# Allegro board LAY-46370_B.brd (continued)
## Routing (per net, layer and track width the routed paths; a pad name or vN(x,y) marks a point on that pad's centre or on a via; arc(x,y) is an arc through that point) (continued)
DSI_DP3: length 80.5
  TOP w0.091: J1.97 90.29,106.96 90.23,106.9 90.23,106.54 90.54,106.22 v1(90.71,106.22) ; v1(31.53,124.47) 31.69,124.63 31.69,124.99 31.61,125.07 U39.6 U39.5 31.61,127.68 31.89,127.96 31.89,128.8 31.66,129.03 J14.B17
  L3_IN1 w0.084: v1(90.71,106.22) 90.9,106.03 91.22,106.03 91.46,105.79 91.46,104.41 88.76,101.71 65.05,101.71 47.69,119.08 36.19,119.08 31.69,123.59 31.69,124.31 v1(31.53,124.47)
DSI_EN: length 58.2
  TOP w0.102: v1(76.4,113.07) 76.82,112.65 76.82,111.21 76.69,111.08 J1.30
  TOP w0.109: J14.A11 36.06,134.06 37.18,135.17 45.34,135.17 49.73,130.79 v1(49.73,124.44)
  BOTTOM w0.109: v1(76.4,113.07) 76.32,112.98 74.17,112.98 71.31,115.84 58.33,115.84 v1(49.73,124.44)
DSI_NINT: length 3.4
  TOP w0.102: J14.B9 38.06,126.72 R304.1
DSI_PWM: length 3.3
  TOP w0.102: R305.1 38.86,126.5 J14.B8
DSI_TS_NINT: length 48.6
  TOP w0.102: v1(38.06,124.96) 37.81,125.2 R304.2 ; v1(76.39,111.49) 76.29,111.39 J1.28
  BOTTOM w0.109: v1(38.06,124.96) 38.06,124.13 47.58,114.61 57.64,114.61 63.7,108.55 73.45,108.55 v1(76.39,111.49)
DSI_TS_SCL: length 3.6
  TOP w0.102: J14.B11 36.46,127.27 R167.1
DSI_TS_SDA: length 3.5
  TOP w0.102: J14.B10 37.26,127.01 R166.1
EARC_N_HPD: length 83.4
  TOP w0.091: TP88.1 160.81,132.73 160.81,132.42 159.72,131.33 159.72,125.54 126.52,92.33 126.52,78.56 120.63,72.67 116.59,72.67 116.53,72.6 J4.53
  TOP w0.102: C162.1 160.8,133.85 160.8,133.53 TP88.1
EARC_P_UTIL: length 83.4
  TOP w0.091: J4.55 116.53,73 116.59,72.94 120.52,72.94 126.25,78.67 126.25,92.44 159.45,125.65 159.45,131.44 160.54,132.53 160.54,132.88 160.33,133.1 TP87.1
  TOP w0.102: TP87.1 160.42,133.66 160.42,134.01 C161.1
ECSPI2_MISO: length 73
  TOP w0.109: J4.37 116.47,69.4 116.5,69.37 146.8,69.37 158.22,80.79 161.18,80.79 165.26,76.71 179.11,76.71 180.45,75.37 U55.4
ECSPI2_MISO_3V3: length 8.3
  TOP w0.109: J21.21 187.14,77.56 184.95,75.37 U55.8
ECSPI2_MOSI: length 72.7
  TOP w0.102: U55.3 181.46,75.77 181.4,75.71 180.81,75.71 v1(180.36,76.16)
  TOP w0.109: J4.35 146.88,69 158.27,80.4 160.91,80.4 165.18,76.14 v1(178.95,76.14)
  BOTTOM w0.102: v1(178.95,76.14) 178.97,76.16 v1(180.36,76.16)
ECSPI2_MOSI_3V3: length 9.9
  TOP w0.109: J21.19 188.05,80.1 185.83,77.87 185.83,76.74 184.87,75.77 U55.9
ECSPI2_SCLK: length 72.7
  TOP w0.109: J4.31 147.34,68.2 158.83,79.69 160.58,79.69 165.3,74.97 U55.5
ECSPI2_SCLK_3V3: length 7.4
  TOP w0.109: U55.7 186.57,74.97 186.61,75.02 J21.23
ECSPI2_SS0: length 72.8
  TOP w0.102: U55.2 v1(181.13,76.17)
  TOP w0.109: v1(178.94,75.5) 165.27,75.5 160.77,80 158.42,80 147.03,68.6 J4.33
  BOTTOM w0.102: v1(181.13,76.17) 180.45,75.5 v1(178.94,75.5)
ECSPI2_SS0_3V3: length 27
  TOP w0.109: U55.10 184.54,76.17 185.25,76.88 185.25,78.14 188.51,81.39 198.27,81.39 198.78,80.89 198.78,76.14 197.66,75.02 J21.24
EN_SNK1: length 20.9
  TOP w0.102: R64.2 49.91,24.63 Q2.3
  TOP w0.109: v1(50.94,28.33) 50.94,28.26 51.71,27.49 51.71,25.94 51.49,25.72 R65.1 49.93,25.72 R64.2
  TOP w0.203: U14.F1 60.51,34.75 v1(60.69,34.93)
  BOTTOM w0.109: v1(60.69,34.93) 61.52,34.09 61.52,33.5 60.83,32.81 58.41,32.81 53.94,28.33 v1(50.94,28.33)
EN_SRC1: length 2.2
  TOP w0.203: U14.G1 60.48,35.49 R55.2
ENET1_EVENT_IN: length 3
  TOP w0.109: v1(105.05,67.08) 104.65,67.08 R317.2
  BOTTOM w0.102: TP42.1 105.62,67.08 v1(105.05,67.08)
ENET1_EVENT_OUT: length 1.8
  TOP w0.109: v1(105.05,66.5) 105.02,66.5 R318.2
  BOTTOM w0.102: v1(105.05,66.5) 104.33,66.5 TP56.1
ENET1_MDC: length 55.1
  TOP w0.102: J3.86 105.82,65.28 106.59,66.04 v1(106.64,66.04)
  TOP w0.109: R110.2 v1(89.34,25.64)
  L6_IN2 w0.114: v1(89.34,25.64) 89.97,25.64 93.07,28.74 93.07,40.26 109.52,56.71 109.52,64.32 107.56,66.28 106.87,66.28 v1(106.64,66.04)
ENET1_MDIO: length 52.6
  TOP w0.102: v1(106.61,65.46) 106.54,65.46 106.11,65.02 106.11,64.03 106.22,63.92 J3.88
  TOP w0.109: R111.2 v1(89.24,27.62) 89.25,27.63 R100.1
  L6_IN2 w0.114: v1(106.61,65.46) 106.77,65.3 108.15,65.3 109.14,64.31 109.14,57.04 92.69,40.59 92.69,29.77 90.54,27.62 v1(89.24,27.62)
ENET1_NINT: length 48.5
  TOP w0.102: U26.31 79.37,30.49 v1(77.39,32.47)
  TOP w0.109: U4.12 117.33,33.8 v1(116.72,34.4) ; R114.1 76.72,34.67 76.72,33.13 v1(77.39,32.47)
  BOTTOM w0.109: v1(116.72,34.4) 116.44,34.12 79.03,34.12 v1(77.39,32.47)
ENET1_NRST: length 41.4
  TOP w0.109: U26.12 85.75,27.29 86.56,26.48 86.56,24.18 v1(86.9,23.83) R113.1 ; v1(110,24.9) 113.57,28.46 113.57,32.23 113.92,32.58 U4.14
  BOTTOM w0.109: v1(86.9,23.83) 87.3,23.44 90.44,23.44 90.6,23.6 108.7,23.6 v1(110,24.9)
ENET1_RD0: length 39.5
  TOP w0.102: v1(106.61,64.88) 106.65,64.88 107.06,64.47 107.06,63.84 107.02,63.81 J3.92
  TOP w0.109: R105.2 v1(82.83,37.57)
  L6_IN2 w0.114: v1(82.83,37.57) 82.83,37.95 103.87,58.99 103.87,62.17 106.58,64.88 v1(106.61,64.88)
ENET1_RD1: length 38.9
  TOP w0.109: R103.2 83.92,37.65 v1(83.95,37.67) ; J3.94 107.42,63.81 107.33,63.91 107.33,64.57 v1(107.44,64.68)
  L6_IN2 w0.114: v1(83.95,37.67) 83.95,38.44 104.18,58.67 104.18,61.14 107.28,64.24 107.28,64.52 v1(107.44,64.68)
ENET1_RD2: length 38.5
  TOP w0.109: J3.96 107.82,64.05 v1(107.78,64.1) ; R102.2 87.76,35.34 v1(87.71,35.39)
  L6_IN2 w0.114: v1(107.78,64.1) 105.57,61.89 105.57,59.39 87.71,41.52 v1(87.71,35.39)
ENET1_RD3: length 42.5
  TOP w0.109: v1(108.02,64.69) 108.22,64.49 J3.98 ; v1(88.64,35.41) 88.99,35.05 R106.2
  L6_IN2 w0.114: v1(108.02,64.69) 108.23,64.48 108.23,63.88 106,61.65 106,59.22 88.21,41.43 88.21,38.8 88.34,38.68 88.84,38.68 88.97,38.55 88.97,38.29 88.84,38.17 88.34,38.17 88.21,38.04 88.21,37.79 88.34,37.66 88.84,37.66 88.97,37.53 88.97,37.28 88.84,37.15 88.34,37.15 88.21,37.02 88.21,35.84 v1(88.64,35.41)
ENET1_RX_CTL: length 41
  TOP w0.109: v1(107.79,59.52) 107.79,59.69 107.82,59.72 J3.95 ; v1(88.91,39.37) 82.86,39.37 80.39,36.9 R107.2
  L6_IN2 w0.114: v1(107.79,59.52) 107.33,59.06 106.37,59.06 88.91,41.61 v1(88.91,39.37)
ENET1_RXC: length 40
  TOP w0.102: v1(79.86,36.2) C99.1 R108.2
  TOP w0.109: J3.73 v1(103.42,59.54)
  L6_IN2 w0.114: v1(79.86,36.2) 79.86,36.33 83.01,39.49 83.8,39.49 85.12,40.81 85.12,40.99 84.97,41.14 84.97,41.32 85.15,41.5 85.33,41.5 85.48,41.35 85.66,41.35 85.84,41.53 85.84,41.71 85.66,41.89 85.66,42.07 85.84,42.25 86.02,42.25 86.2,42.07 86.38,42.07 86.56,42.25 86.56,42.43 86.38,42.6 86.38,42.78 86.56,42.96 86.74,42.96 86.92,42.79 87.1,42.79 87.28,42.97 87.28,43.15 87.1,43.32 87.1,43.5 87.28,43.68 87.46,43.68 87.64,43.51 87.82,43.51 88,43.69 88,43.87 87.82,44.04 87.82,44.22 88,44.4 88.18,44.4 88.36,44.23 88.54,44.23 103.42,59.11 v1(103.42,59.54)
ENET1_RXC/PHYAD1: length 8.8
  TOP w0.109: U26.27 81.96,31.54 82.07,31.65 82.07,32.25 80.89,33.43 79.69,33.43 R108.1 78.09,33.96 R119.1 77.73,33.96 77.51,34.19 77.51,35.63 R439.2
ENET1_RXCTL/PHYAD2: length 4.3
  TOP w0.102: R126.1 R107.1
  TOP w0.109: R126.1 81.62,33.17 82.36,32.44 U26.26
ENET1_RXD0/RXDLY: length 6.9
  TOP w0.102: U26.25 82.76,33.9 R125.1 ; R118.2 R105.1
  TOP w0.109: R125.1 83.24,33.98 83.34,34.08 83.34,35.7 R105.1
ENET1_RXD1/TXDLY: length 7.2
  TOP w0.102: R103.1 R117.2 85.01,35.64 84.59,35.23 84.59,34.11 84.45,33.97 R124.1
  TOP w0.109: R124.1 83.16,33.17 U26.24
ENET1_RXD2/PLLOFF: length 6
  TOP w0.102: R120.2 83.56,32.21 U26.23
  TOP w0.109: R120.2 R128.1 R102.1
ENET1_RXD3/PHYAD0: length 8.9
  TOP w0.102: R127.2 90.09,33.96 R106.1
  TOP w0.109: U26.22 83.96,32.01 85.08,33.13 88.16,33.13 R106.1 ; R438.1 91.15,33.96 R127.2
ENET1_TD0: length 44.4
  TOP w0.102: v1(105.07,55.94) 103.92,57.09 103.92,59.69 103.82,59.78 J3.75
  TOP w0.109: v1(91.52,30.05) 91.29,30.29 90.29,30.29 89.15,29.15 86.22,29.15 85.68,29.69 U26.18
  L6_IN2 w0.114: v1(105.07,55.94) 105.07,55.81 90.64,41.39 90.64,30.92 91.51,30.05 v1(91.52,30.05)
ENET1_TD1: length 43
  TOP w0.102: J3.77 104.22,59.8 104.15,59.72 104.15,57.47 v1(105.08,56.54)
  TOP w0.109: U26.17 85.57,29.29 85.98,28.88 89.52,28.88 v1(90.39,29.76)
  L6_IN2 w0.114: v1(105.08,56.54) 105.04,56.54 90.3,41.81 90.3,29.85 v1(90.39,29.76)
ENET1_TD2: length 43.4
  TOP w0.102: J3.81 105.02,59.7 105.11,59.61 v1(105.11,57.18)
  TOP w0.109: U26.16 85.55,28.89 85.83,28.61 89.93,28.61 v1(90.39,29.08)
  L6_IN2 w0.114: v1(105.11,57.18) 105.09,57.18 89.95,42.04 89.95,29.57 90.39,29.13 v1(90.39,29.08)
ENET1_TD3: length 44.9
  TOP w0.102: v1(106.69,57.41) 106.63,57.41 105.52,58.52 105.52,59.83 105.42,59.93 J3.83
  TOP w0.109: U26.15 85.48,28.49 85.62,28.34 90.38,28.34 90.98,28.94 v1(90.98,29.05)
  L6_IN2 w0.114: v1(90.98,29.05) 91.44,29.05 92.29,29.91 92.29,41.03 106.69,55.43 v1(106.69,57.41)
ENET1_TX_CTL: length 43.6
  TOP w0.102: v1(106.66,57.99) 106.65,57.99 105.82,58.82 J3.85
  TOP w0.109: U26.19 85.65,30.09 86.33,29.41 88.92,29.41 90.2,30.69 v1(91.51,30.69)
  L6_IN2 w0.114: v1(91.51,30.69) 91.54,30.69 91.94,31.09 91.94,41.37 106.25,55.67 106.25,57.6 106.65,57.99 v1(106.66,57.99)
ENET1_TXC: length 43.4
  TOP w0.102: J3.87 106.22,60 106.13,59.91 106.13,59.13 v1(106.67,58.59)
  TOP w0.109: v1(91.49,31.28) 90.32,31.28 88.68,29.65 86.49,29.65 85.65,30.49 U26.20
  L6_IN2 w0.114: v1(91.49,31.28) 91.04,31.74 91.04,41.19 105.82,55.97 105.82,57.78 106.63,58.59 v1(106.67,58.59)
ENET_MDC: length 73.4
  TOP w0.102: v1(110.94,71.73) 110.94,71.86 111.29,72.2 J4.52
  TOP w0.109: v1(107.78,26.45) 107.69,26.35 R79.2 ; v1(89.28,24.51) 89.22,24.57 R424.2
  L6_IN2 w0.114: v1(110.94,71.73) 110.94,71.77 111.42,72.25 112.35,72.25 113.06,71.54 113.06,41.47 109.6,38.01 109.6,34.81 109.04,34.25 109.04,27.69 107.8,26.45 v1(107.78,26.45)
  BOTTOM w0.109: v1(89.28,24.51) 89.69,24.1 105.44,24.1 v1(107.78,26.45)
ENET_MDIO: length 74.5
  TOP w0.102: J4.54 111,72.6 110.36,71.96 v1(110.36,71.61) ; R85.1 v1(107.89,27.23)
  TOP w0.109: R80.2 107.12,27.64 107.53,27.23 v1(107.89,27.23) ; R425.2 v1(89.33,26.67)
  L6_IN2 w0.114: v1(107.89,27.23) 108.45,27.8 108.45,34.36 109.02,34.93 109.02,38.12 112.64,41.74 112.64,70.69 112.12,71.22 110.68,71.22 110.36,71.54 v1(110.36,71.61)
  BOTTOM w0.109: v1(107.89,27.23) 105.04,24.39 91.61,24.39 v1(89.33,26.67)
ENET_NINT: length 29
  TOP w0.109: U4.13 116.72,33.59 v1(116.68,33.62) ; R84.1 96.77,35.61 v1(96.77,33.58) 97.76,32.59 97.76,31.37 98.67,30.46 U23.31
  BOTTOM w0.109: v1(116.68,33.62) 116.51,33.8 96.99,33.8 v1(96.77,33.58)
ENET_NRST: length 20.1
  TOP w0.109: U4.15 114.29,32.18 113.89,31.78 113.89,28.1 110.13,24.35 106.59,24.35 106.33,24.6 R83.1 105.64,25.16 105.18,25.63 105.18,26.52 104.44,27.26 U23.12
ENET_RD0: length 55.4
  TOP w0.102: v1(111.55,77.75) 111.55,77.81 111.95,78.2 J4.82
  TOP w0.109: R73.2 102.78,34.7 v1(102.77,34.71)
  L6_IN2 w0.114: v1(111.55,77.75) 111.55,78.01 110.97,78.6 109.94,78.6 108.15,76.81 108.15,66.92 110.29,64.78 110.29,46.13 109.61,45.46 109.61,45.28 109.96,44.94 109.96,44.76 109.78,44.58 109.6,44.58 109.25,44.92 109.07,44.92 108.9,44.74 108.9,44.56 109.24,44.22 109.24,44.04 109.06,43.86 108.88,43.86 108.54,44.2 108.36,44.2 104.96,40.81 104.96,37.89 102.77,35.7 v1(102.77,34.71)
ENET_RD1: length 55
  TOP w0.102: J4.84 111.75,78.6 110.97,77.82 v1(110.97,77.76)
  TOP w0.109: R72.2 v1(103.84,34.72)
  L6_IN2 w0.114: v1(110.97,77.76) 110.97,77.9 110.67,78.2 110.16,78.2 108.54,76.59 108.54,66.97 110.66,64.85 110.66,44.77 108.83,42.94 108.65,42.94 108.36,43.23 108.18,43.23 108,43.05 108,42.87 108.29,42.58 108.29,42.4 108.11,42.22 107.93,42.22 107.64,42.51 107.46,42.51 107.28,42.33 107.28,42.15 107.57,41.86 107.57,41.68 107.4,41.5 107.22,41.5 106.93,41.79 106.75,41.79 106.57,41.61 106.57,41.43 106.86,41.14 106.86,40.96 105.59,39.7 105.59,37.94 103.84,36.19 v1(103.84,34.72)
ENET_RD2: length 55.9
  TOP w0.102: v1(110.34,77.75) 110.34,77.84 111.51,79 J4.86
  TOP w0.109: R71.2 v1(104.94,34.63)
  L6_IN2 w0.114: v1(104.94,34.63) 104.94,36.87 107.84,39.77 107.84,39.95 107.46,40.32 107.46,40.5 107.64,40.68 107.82,40.68 108.2,40.31 108.38,40.31 108.56,40.49 108.56,40.67 108.18,41.04 108.18,41.22 108.36,41.4 108.54,41.4 108.92,41.02 109.1,41.02 109.28,41.2 109.28,41.38 108.9,41.76 108.9,41.94 109.08,42.12 109.26,42.12 109.64,41.74 109.82,41.74 110,41.92 110,42.1 109.62,42.48 109.62,42.66 109.8,42.84 109.98,42.84 110.36,42.46 110.54,42.46 111.02,42.95 111.02,65.01 108.99,67.04 108.99,76.4 v1(110.34,77.75)
ENET_RD3: length 54.8
  TOP w0.102: v1(110.86,79.8) 111.38,79.28 112.36,79.28 112.48,79.4 J4.88
  TOP w0.109: R75.2 106.02,34.58 106.46,35.02 106.46,37.71 105.96,38.21 104.65,38.21 v1(104.49,38.05)
  L6_IN2 w0.114: v1(104.49,38.05) 104.25,38.29 104.25,40.72 109.89,46.36 109.89,64.63 107.81,66.71 107.81,76.94 110.67,79.8 v1(110.86,79.8)
ENET_RX_CTL: length 56.2
  TOP w0.102: v1(111.43,76.88) 111.99,76.32 112.32,76.32 112.44,76.2 J4.72
  TOP w0.109: v1(107.13,38.01) 106.63,38.51 103.04,38.51 101.7,37.17 101.7,36.44 101.59,36.33 101.15,36.33 101.04,36.23 101.04,36.03 101.15,35.93 101.59,35.93 101.7,35.83 101.7,35.62 101.59,35.52 101.15,35.52 101.04,35.42 101.04,35.22 101.15,35.12 101.59,35.12 101.7,35.01 R76.2
  L6_IN2 w0.114: v1(107.13,38.01) 111.37,42.25 111.37,65.14 109.39,67.12 109.39,76.07 109.92,76.61 111.16,76.61 v1(111.43,76.88)
ENET_RXC: length 56.8
  TOP w0.102: C81.1 98.44,34.01 R77.2 ; v1(112.07,76.86) 112.33,76.6 J4.74
  TOP w0.109: C81.1 99.77,35.75 102.86,38.84 107.03,38.84 v1(107.92,37.96)
  L6_IN2 w0.114: v1(112.07,76.86) 111.53,76.32 110.14,76.32 109.77,75.96 109.77,67.23 111.69,65.31 111.69,41.73 v1(107.92,37.96)
ENET_TD0: length 58.3
  TOP w0.102: v1(111.38,29.83) 110.94,29.39 104.9,29.39 104.63,29.66 U23.18 ; v1(110.23,73.83) 110.23,73.92 110.57,74.27 112.27,74.27 112.33,74.2 J4.62
  L6_IN2 w0.114: v1(110.23,73.83) 111.44,72.62 112.53,72.62 113.45,71.7 113.45,41.06 110.3,37.91 110.3,30.86 111.32,29.83 v1(111.38,29.83)
ENET_TD1: length 58.8
  TOP w0.102: J4.64 111.35,74.6 111.24,74.71 111.1,74.71 v1(111.08,74.7) ; U23.17 104.71,29.26 104.8,29.16 111.32,29.16 111.99,29.83 111.99,30.21 v1(112.8,31.02)
  L6_IN2 w0.114: v1(112.8,31.02) 112.5,31.32 112.5,37.33 114.56,39.4 114.56,73.07 113.22,74.41 111.3,74.41 111.08,74.63 v1(111.08,74.7)
ENET_TD2: length 61
  TOP w0.102: J4.66 111.59,75 110.88,75.71 v1(110.88,75.77) ; v1(112.81,30.4) 112.42,30.01 112.42,29.66 111.62,28.86 U23.16
  L6_IN2 w0.114: v1(110.88,75.77) 110.88,75.53 111.57,74.84 113.48,74.84 114.98,73.34 114.98,38.98 113.24,37.24 113.24,30.84 112.81,30.41 v1(112.81,30.4)
ENET_TD3: length 60.7
  TOP w0.102: J4.68 112.46,75.4 112.43,75.37 111.86,75.37 111.49,75.74 v1(111.49,75.78) ; v1(112.85,29.7) 111.61,28.46 U23.15
  L6_IN2 w0.114: v1(111.49,75.78) 111.49,75.53 111.74,75.29 113.66,75.29 115.35,73.59 115.35,38.59 113.69,36.93 113.69,30.54 v1(112.85,29.7)
ENET_TX_CTL: length 59.6
  TOP w0.102: J4.56 111.63,73 110.86,73.77 v1(110.86,73.83) ; v1(111.37,30.42) 111.35,30.42 110.55,29.62 105.15,29.62 104.71,30.06 U23.19
  L6_IN2 w0.114: v1(110.86,73.83) 110.86,73.65 111.53,72.97 112.72,72.97 113.82,71.87 113.82,40.85 113.53,40.56 113.53,40.38 113.75,40.16 113.75,39.98 113.57,39.8 113.39,39.8 113.17,40.02 112.99,40.02 112.81,39.84 112.81,39.66 113.03,39.44 113.03,39.26 112.85,39.08 112.67,39.08 112.45,39.31 112.27,39.31 112.09,39.13 112.09,38.95 112.31,38.72 112.31,38.54 112.13,38.36 111.95,38.36 111.73,38.59 111.55,38.59 110.72,37.76 110.72,31.06 v1(111.37,30.42)
ENET_TXC: length 59.4
  TOP w0.102: v1(111.45,73.83) 111.45,73.71 111.86,73.3 112.31,73.3 112.41,73.4 J4.58 ; U23.20 104.98,30.46 105.59,29.85 110.18,29.85 v1(111.38,31.04)
  L6_IN2 w0.114: v1(111.38,31.04) 111.94,31.6 111.94,32.29 111.81,32.41 111.51,32.41 111.38,32.54 111.38,32.79 111.51,32.92 111.81,32.92 111.94,33.05 111.94,33.3 111.81,33.43 111.51,33.43 111.38,33.56 111.38,33.81 111.51,33.94 111.81,33.94 111.94,34.06 111.94,34.32 111.81,34.44 111.51,34.44 111.38,34.57 111.38,34.83 111.51,34.95 111.81,34.95 111.94,35.08 111.94,35.33 111.81,35.46 111.51,35.46 111.38,35.59 111.38,35.84 111.51,35.97 111.81,35.97 111.94,36.1 111.94,36.35 111.81,36.48 111.51,36.48 111.38,36.6 111.38,36.91 114.19,39.72 114.19,71.9 112.8,73.29 111.68,73.29 111.45,73.52 v1(111.45,73.83)
ETH1_1GB_LINK/ACTIVE: length 20.5
  TOP w0.254: R109.1 75.45,18.39 75.45,13.08 79.25,9.28 79.25,6.1 J9.11
ETH1_10M_100M_LINK/ACTIVE: length 18.9
  TOP w0.254: R104.1 89.45,12.18 85.62,8.35 85.62,3.51 J9.13
ETH1_AVDD1V0: length 8.4
  TOP w0.203: U26.8 v1(83.56,25.38) ; U26.3 v1(81.56,25.32) ; U26.38 79.47,27.69 79.38,27.6 v1(79.31,27.6)
  TOP w0.381: L7.2 86.89,30.22 v1(86.76,30.09)
  BOTTOM w0.381: C84.1 79.64,27.93 v1(79.31,27.6) ; C339.1 86.97,30.3 v1(86.76,30.09) ; v1(83.56,25.38) 83.31,25.62 C85.1 83.3,26.19 C86.1 81.68,25.44 v1(81.56,25.32)
ETH1_AVDD3V3: length 11.7
  TOP w0.203: U26.40 v1(80.1,26.17) ; U26.11 v1(85.02,26.41)
  TOP w0.381: v1(80.1,26.17) 79.92,25.99 L6.2
  BOTTOM w0.381: C88.1 85.15,26.54 v1(85.02,26.41) 85.02,25.48 84.24,24.71 80.83,24.71 80.1,25.44 v1(80.1,26.17) 79.99,26.28 C87.1
ETH1_CLK125_OUT: length 2
  TOP w0.109: U26.35 78.59,28.89 TP35.1
ETH1_DVDD1V0: length 6.5
  TOP w0.203: U26.21 84.36,31.67 v1(84.6,31.92)
  TOP w0.381: L8.2 87.45,31.88 87.07,32.27 84.95,32.27 v1(84.6,31.92)
  BOTTOM w0.381: v1(84.6,31.92) 85.1,31.41 C93.1 85.11,31.15 C14.1
ETH1_DVDD3V3: length 12.3
  TOP w0.203: v1(80.87,32.04) 80.87,32 81.16,31.71 U26.29
  TOP w0.381: R115.1 v1(74.85,34.13) ; v1(80.87,32.04) 80.34,32.57 78.45,32.57 77.12,33.9 77.12,35.51 v1(76.85,35.78) L5.2 ; R116.1 v1(74.85,27.71)
  BOTTOM w0.381: v1(80.87,32.04) 80.59,31.76 C89.1 81.22,30.76 81.61,31.15 C90.1
ETH1_LED0/CFG_EXT: length 6.2
  TOP w0.102: R115.2 R121.1
  TOP w0.109: R121.1 76.21,32.96 79.08,30.09 U26.32
ETH1_LED1/CFGLDO0: length 42.3
  TOP w0.109: C100.1 R123.1 v1(76.82,30.92) 77.1,30.92 78.33,29.69 U26.33
  L6_IN2 w0.114: v1(76.82,30.92) 77.45,30.29 77.45,19.18 75.43,17.16 75.43,13.24 79.65,9.02 82.65,9.02 J9.14
ETH1_LED2/CFGLDO1: length 36.7
  TOP w0.109: R116.2 R122.1 76.2,28.81 C101.1 v1(76.91,29.86) 77.57,29.86 78.14,29.29 U26.34
  L6_IN2 w0.114: J9.12 79.38,3.69 79.38,8.68 74.99,13.08 74.99,17.27 77.08,19.36 77.08,29.7 v1(76.91,29.86)
ETH1_MDC: length 4.7
  TOP w0.109: U26.13 86.01,27.69 86.89,26.82 86.89,26.2 R110.1 R424.1
ETH1_MDIO: length 3.6
  TOP w0.109: R425.1 R111.1 86.98,28.09 U26.14
ETH1_TRX0_N: length 15
  TOP w0.091: U26.2 81.16,25.61 81.09,25.54 81.09,22.84 79.82,21.57 79.82,20.82 79.93,20.71 U28.9 U28.2 79.93,18.95 79.82,18.83 79.82,17.99 78.01,16.19 78.01,14.91 78.4,14.52 78.9,14.52 79.23,14.85 J9.3
ETH1_TRX0_P: length 14.9
  TOP w0.091: U26.1 80.76,25.61 80.82,25.54 80.82,22.95 79.55,21.68 79.55,20.82 79.43,20.71 U28.10 U28.1 79.43,18.95 79.55,18.83 79.55,18.1 77.74,16.3 77.74,14.8 78.29,14.25 78.29,13.38 J9.2
ETH1_TRX1_N: length 14.4
  TOP w0.091: U26.5 82.36,25.61 82.29,25.54 82.29,22.62 81.31,21.64 81.31,20.79 81.43,20.67 U28.6 U28.5 81.43,18.95 81.32,18.83 81.32,17.34 80.53,16.55 80.53,14.88 80.91,14.51 81.32,14.51 81.77,14.96 J9.5
ETH1_TRX1_P: length 14.4
  TOP w0.091: J9.4 80.79,13.34 80.79,14.24 80.26,14.77 80.26,16.66 81.05,17.45 81.05,18.83 80.93,18.95 U28.4 U28.7 80.93,20.69 81.05,20.8 81.05,21.75 82.02,22.73 82.02,25.54 81.96,25.61 U26.4
ETH1_TRX2_N: length 14.2
  TOP w0.091: J9.7 84.31,14.86 83.99,14.53 83.6,14.53 83.13,15 83.13,16.89 83.84,17.59 83.84,18.83 83.96,18.95 U27.2 U27.9 83.96,20.68 83.84,20.8 83.84,22.65 83.09,23.4 83.09,25.54 83.16,25.61 U26.7
ETH1_TRX2_P: length 14.3
  TOP w0.091: U26.6 82.76,25.61 82.82,25.54 82.82,23.28 83.57,22.54 83.57,20.81 83.46,20.69 U27.10 U27.1 83.46,18.95 83.57,18.83 83.57,17.7 82.87,17 82.87,14.89 83.41,14.34 83.41,13.42 J9.6
ETH1_TRX3_N: length 14.2
  TOP w0.091: U26.10 84.36,25.61 84.29,25.54 84.29,23.72 85.34,22.68 85.34,20.8 85.46,20.68 U27.6 U27.5 85.46,18.95 85.34,18.83 85.34,17.03 85.55,16.82 85.55,14.93 85.93,14.56 86.42,14.56 86.85,15 J9.9
ETH1_TRX3_P: length 14.2
  TOP w0.091: U26.9 83.96,25.61 84.02,25.54 84.02,23.61 85.07,22.56 85.07,20.8 84.96,20.69 U27.7 U27.4 84.96,18.95 85.07,18.83 85.07,16.92 85.29,16.71 85.29,14.82 85.87,14.24 85.87,13.34 J9.8
ETH1_VDD1V0: length 14.3
  TOP w0.203: v1(79.97,31.99) 80.12,31.99 80.76,31.36 U26.30
  TOP w0.381: L7.1 L8.1 v1(88.47,32.05)
  BOTTOM w0.381: C95.1 79.26,31.28 C96.1 v1(79.97,31.99) 80.01,31.99 80.76,32.74 87.78,32.74 v1(88.47,32.05)
ETH1_VDDIO: length 9.6
  TOP w0.203: U26.28 v1(81.56,31.98)
  TOP w0.381: v1(89.5,35.38) 90.09,34.79 R127.1 ; v1(82.06,37.54) 82.06,37.32 R118.1 ; R101.2 v1(86.62,36.2) ; R117.1 v1(85.01,37.56) ; v1(85.43,35.32) 85.31,35.19 R120.1 ; TP34.1 78.08,37.61 v1(78.08,37.56) R439.1 ; R100.2 v1(90.66,26.95)
  BOTTOM w0.381: v1(81.56,31.98) 82.39,31.98 82.98,31.39 C91.1 82.98,31.15 C92.1
ETH1_XTALI: length 7.6
  TOP w0.109: U26.36 79.09,28.49 78.46,27.86 78.46,26.03 78.25,25.83 C97.1 77.49,25.54 75.82,25.54 Y2.1
ETH1_XTALO: length 6.4
  TOP w0.109: Y2.3 76.74,24.94 C98.1 78.2,24.94 78.74,25.48 78.74,27.66 79.17,28.09 U26.37
ETH_AVDD1V0: length 6.9
  TOP w0.203: U23.8 v1(102.62,25.37) ; U23.38 v1(98.29,27.66) ; U23.3 v1(100.62,25.38)
  TOP w0.381: L3.2 v1(106.12,32.36)
  BOTTOM w0.381: v1(100.62,25.38) 100.75,25.51 C66.1 ; C65.1 102.07,25.91 v1(102.62,25.37) ; v1(98.29,27.66) 98.38,27.74 C67.1 99.06,27.75 C333.1
ETH_AVDD3V3: length 12.4
  TOP w0.203: v1(98.42,26.61) 98.42,26.62 98.66,26.86 U23.40 ; U23.11 104.08,26.49 v1(104.2,26.37)
  TOP w0.381: v1(98.42,26.61) 98.42,25.08 L2.2
  BOTTOM w0.381: v1(98.42,26.61) 98.48,26.67 C68.1 99.03,25.94 100.18,24.79 103.04,24.79 104.2,25.95 v1(104.2,26.37) 104.15,26.42 C69.1
ETH_CLK125_OUT: length 2.1
  TOP w0.109: TP33.1 97.62,28.86 U23.35
ETH_CT: length 4.3
  TOP w0.254: C75.1 96.8,18.87 J8.1
ETH_CT1: length 4.5
  TOP w0.254: C94.1 76.69,18.4 J9.1
ETH_DVDD1V0: length 6.1
  TOP w0.203: v1(103.9,31.74) 103.7,31.74 103.42,31.46 U23.21
  TOP w0.381: v1(103.9,31.74) 104.86,31.74 L4.2
  BOTTOM w0.381: C334.1 105.47,30.59 C74.1 104.41,31.24 v1(103.9,31.74)
ETH_DVDD3V3: length 6.9
  TOP w0.203: U23.29 100.22,31.64 v1(99.91,31.95)
  TOP w0.381: v1(93.62,35.08) L1.2 93.64,35.76 R86.1 ; R87.1 v1(94.1,29.2)
  BOTTOM w0.381: v1(99.91,31.95) 99.91,30.99 99.67,30.75 C70.1 100.51,30.17 100.91,30.57 C71.1
ETH_TRX0_N: length 14.5
  TOP w0.091: J8.3 99.34,14.67 99.21,14.54 98.66,14.54 98.14,15.07 98.14,15.95 100.2,18.01 100.2,18.83 100.31,18.95 U25.2 U25.9 100.31,20.71 100.22,20.8 100.22,23.06 100.15,23.13 100.15,25.5 100.22,25.57 U23.2
ETH_TRX0_P: length 14.6
  TOP w0.091: J8.2 98.55,13.54 98.55,14.27 98.44,14.39 97.87,14.96 97.87,16.06 99.93,18.12 99.93,18.83 99.81,18.95 U25.1 U25.10 99.81,20.7 99.95,20.84 99.95,22.95 99.88,23.02 99.88,25.5 99.82,25.57 U23.1
ETH_TRX1_N: length 14.1
  TOP w0.091: U23.5 101.42,25.57 101.35,25.5 101.35,24.25 101.7,23.9 101.7,20.79 101.81,20.67 U25.6 U25.5 101.81,18.95 101.7,18.83 101.7,17.89 100.72,16.92 100.72,15.02 101.17,14.57 101.66,14.57 101.88,14.79 J8.5
ETH_TRX1_P: length 14.2
  TOP w0.091: J8.4 101,13.45 101,14.36 100.46,14.91 100.46,17.03 101.43,18 101.43,18.83 101.31,18.95 U25.4 U25.7 101.31,20.67 101.43,20.79 101.43,23.78 101.08,24.13 101.08,25.51 101.02,25.57 U23.4
ETH_TRX2_N: length 14.8
  TOP w0.091: U23.7 102.22,25.57 102.15,25.5 102.15,24.98 104.22,22.91 104.22,20.84 104.32,20.73 U24.9 U24.2 104.32,18.95 104.21,18.83 104.21,17.57 103.19,16.55 103.19,14.95 103.55,14.6 104.13,14.6 104.42,14.89 J8.7
ETH_TRX2_P: length 14.9
  TOP w0.091: U23.6 101.82,25.57 101.88,25.5 101.88,24.87 103.95,22.8 103.95,20.83 103.82,20.71 U24.10 U24.1 103.82,18.95 103.94,18.83 103.94,17.68 102.93,16.66 102.93,14.84 103.42,14.34 103.42,13.33 J8.6
ETH_TRX3_N: length 14.6
  TOP w0.091: U23.10 103.42,25.57 103.35,25.5 103.35,25.2 105.71,22.85 105.71,20.79 105.82,20.68 U24.6 U24.5 105.82,18.95 105.71,18.83 105.71,15.02 106.15,14.58 106.78,14.58 106.96,14.76 J8.9
ETH_TRX3_P: length 14.6
  TOP w0.091: J8.8 106.03,13.39 106.03,14.33 105.44,14.91 105.44,18.83 105.32,18.95 U24.4 U24.7 105.32,20.71 105.44,20.82 105.44,22.74 103.08,25.09 103.08,25.5 103.02,25.57 U23.9
ETH_VDD1V0: length 14.9
  TOP w0.254: v1(99.07,31.35) 99.3,31.12 U23.30
  TOP w0.381: L4.1 107.12,31.57 L3.1 107.14,31.6 v1(107.88,31.6)
  BOTTOM w0.381: v1(99.07,31.35) 98.93,31.48 C77.1 98.39,31.48 C76.1 98.94,33.14 106.34,33.14 v1(107.88,31.6)
ETH_VDDIO: length 13.3
  TOP w0.203: U23.28 100.62,31.92 v1(100.59,31.95)
  TOP w0.381: R91.1 v1(107.1,35.02) 107.11,35.01 R90.1 109.73,34.01 TP32.1 v1(109.75,33.2) ; v1(109.76,27.74) R85.2 109.15,27.01 109.16,27 R70.2 ; v1(103.42,37.12) 103.66,36.88 R89.1 104.75,36.51 R88.1
  BOTTOM w0.381: v1(100.59,31.95) 101.01,31.95 102.26,30.69 C72.1 102.27,30.58 C73.1
ETH_XTALI: length 6.2
  TOP w0.109: Y1.1 94.33,27.52 95.06,26.79 96.54,26.79 C79.1 97.39,27.27 97.49,27.38 97.49,27.97 97.97,28.46 U23.36
ETH_XTALO: length 5
  TOP w0.109: U23.37 98.76,28.06 98.66,28.16 98.1,28.16 97.77,27.83 97.77,27.02 C80.1 95.97,26.27 Y1.3
EX_POR_B: length 4.6
  TOP w0.109: U1.24 181.15,87.52 180.96,87.71 179.51,87.71 179.12,87.32 R407.2 178.35,88.48 U2.4
EXP_P0_7: length 56
  TOP w0.102: J21.22 195.62,77.56 v1(193.4,77.56) ; U1.8 v1(181.65,82.45)
  TOP w0.109: v1(181.65,82.45) 181.13,81.93 181.13,81.05 180.51,80.43 163.09,80.43 161.95,81.57 v1(158.5,81.57) ; R142.2 v1(157.37,91.68)
  L6_IN2 w0.114: v1(157.37,91.68) 157.9,91.15 157.9,82.17 v1(158.5,81.57)
  BOTTOM w0.109: v1(193.4,77.56) 193.4,77.67 189.16,81.91 182.18,81.91 v1(181.65,82.45)
EXP_P1_0: length 18.3
  TOP w0.102: v1(182.96,82.4) 182.65,82.71 U1.10 ; J21.12 v1(193.37,90.26)
  BOTTOM w0.109: v1(193.37,90.26) 189.53,90.26 187.64,88.36 187.64,85.92 184.75,83.03 183.59,83.03 v1(182.96,82.4)
EXP_P1_1: length 11.1
  TOP w0.102: v1(183.6,82.38) 183.15,82.83 U1.11 ; J21.13 188.76,87.72 v1(188.26,87.21)
  BOTTOM w0.109: v1(183.6,82.38) 184.64,82.38 188.26,86.01 v1(188.26,87.21)
EXP_P1_2: length 7.8
  TOP w0.109: J21.15 188.08,85.18 186.16,83.26 U1.12
EXP_P1_3: length 12.6
  TOP w0.109: U1.13 186.38,83.97 188.61,86.19 193.43,86.19 194.45,85.18 J21.16
EXP_P1_4: length 20.3
  TOP w0.109: U1.14 185.02,84.47 185.02,84.46 186.21,84.46 188.34,86.59 197.15,86.59 198.14,85.61 198.14,83.06 197.71,82.64 J21.18
EXP_P1_5: length 23.7
  TOP w0.102: J21.29 v1(186.01,67.4)
  TOP w0.109: v1(185.81,84.9) 185.74,84.97 U1.15
  L6_IN2 w0.114: v1(186.01,67.4) 185.81,67.6 v1(185.81,84.9)
EXP_P1_6: length 26.1
  TOP w0.102: J21.31 187.43,64.86 v1(187.39,64.9)
  TOP w0.109: v1(185.8,85.56) 185.7,85.47 U1.16
  L6_IN2 w0.114: v1(187.39,64.9) 187.39,67.01 186.29,68.12 186.29,85.07 v1(185.8,85.56)
EXP_P1_7: length 28.8
  TOP w0.102: J21.33 v1(188.33,62.32)
  TOP w0.109: v1(185.84,86.18) 185.63,85.97 U1.17
  L6_IN2 w0.114: v1(188.33,62.32) 188.33,66.61 186.68,68.27 186.68,85.34 v1(185.84,86.18)
EXT_3V3_PG: length 3.4
  BOTTOM w0.254: TP71.1 43.89,105.66 U64.7
EXT_PWREN1: length 169.9
  TOP w0.109: U1.1 179.75,86.47 179.49,86.21 177.28,86.21 173.32,90.17 v1(173.32,100.72)
  L6_IN2 w0.114: v1(48.34,115.63) 48.27,115.57 v1(48.27,104.83)
  BOTTOM w0.102: R271.1 v1(48.27,104.83)
  BOTTOM w0.109: v1(173.32,100.72) 173.32,108.08 164.69,116.71 80.92,116.71 76.82,112.61 74.16,112.61 71.25,115.52 48.46,115.52 v1(48.34,115.63)
EXT_PWREN2: length 224.7
  TOP w0.109: v1(172.61,100.71) 172.61,90.23 177.03,85.82 179.51,85.82 179.66,85.97 U1.2 ; v1(69.13,108.99) 69.13,98.58 55.52,84.97 16.75,84.97 v1(15.42,83.64)
  BOTTOM w0.102: R281.1 17.77,98.35 R450.1
  BOTTOM w0.109: v1(172.61,100.71) 172.61,108.27 164.5,116.38 80.99,116.38 76.92,112.31 74.79,112.31 73.91,111.43 73.91,111.19 71.71,108.99 v1(69.13,108.99) ; R450.1 17.76,97.46 15.42,95.12 v1(15.42,83.64)
FAN_EN: length 39.1
  TOP w0.109: v1(179.69,83.48) 179.69,84.2 179.96,84.47 U1.5
  TOP w0.203: R456.1 v1(180.93,119.73)
  L3_IN1 w0.114: v1(179.69,83.48) 180.45,84.24 180.45,119.25 v1(180.93,119.73)
FRS_EN: length 1.4
  TOP w0.109: TP97.1 33.61,17.35 U11.1
FRS_EN1: length 17.2
  TOP w0.109: v1(54.57,26.93) 54.57,30.23 57.49,33.15 U14.B6 ; U17.1 46.54,25.93 v1(46.89,25.57)
  BOTTOM w0.109: v1(46.89,25.57) 47.6,26.29 53.93,26.29 v1(54.57,26.93)
FT_BOOT_MODE0: length 5.2
  TOP w0.102: v1(10.67,74.61) v1(9.11,74.61)
  BOTTOM w0.102: R386.2 9.13,74.58 v1(9.11,74.61)
  BOTTOM w0.109: U20.1 10.37,77.13 10.74,76.76 10.74,74.68 v1(10.67,74.61)
FT_BOOT_MODE1: length 3.8
  BOTTOM w0.109: U20.4 9.17,76.67 9.3,76.54 9.3,75.38 10.23,74.45 R387.2
FT_BOOT_MODE2: length 7.2
  TOP w0.102: v1(8.56,79.26) 11.69,76.13 11.69,75.59 11.34,75.24 v1(11.34,74.64)
  BOTTOM w0.102: R388.2 v1(11.34,74.64)
  BOTTOM w0.109: U20.8 v1(8.56,79.26)
FT_BOOT_MODE3: length 8
  TOP w0.102: v1(12.47,74.73) 12.47,76.19 10.01,78.66 v1(10.01,79.94)
  BOTTOM w0.102: R389.2 v1(12.47,74.73)
  BOTTOM w0.109: U20.11 9.97,79.91 v1(10.01,79.94)
FT_EECS: length 2.1
  TOP w0.109: U60.63 5.32,18.2 R240.2
FT_EEDATA: length 2.1
  TOP w0.109: U60.61 5.45,19.2 R236.2
FT_GPIO1: length 42.4
  TOP w0.109: v1(30.43,57.62) 31.55,58.75 J25.25 ; v1(20.79,24.69) 20.79,24.56 20.42,24.2 U60.30
  L6_IN2 w0.114: v1(30.43,57.62) 30,57.19 30,45.47 25.78,41.25 25.78,30.73 20.79,25.73 v1(20.79,24.69)
FT_GPIO2: length 43.3
  TOP w0.102: v1(32.35,59.08) 32.33,59.08 31.92,59.49 31.92,59.94 31.95,59.97 J25.27
  TOP w0.109: v1(21.39,24.7) 21.39,24.79 20.98,25.2 U60.32
  L6_IN2 w0.114: v1(21.39,24.7) 21.39,25.63 26.31,30.54 26.31,41.05 31.12,45.86 31.12,57.85 v1(32.35,59.08)
FT_GPIO3: length 45.8
  TOP w0.109: v1(32.37,58.45) 32.86,58.94 32.86,59.95 32.75,60.06 J25.31 ; v1(22.08,25.56) 21.75,25.56 20.95,26.36 17.05,26.36 16.77,26.64 U60.33
  L6_IN2 w0.114: v1(22.08,25.56) 22.23,25.56 26.79,30.12 26.79,40.88 31.58,45.67 31.58,57.66 v1(32.37,58.45)
FT_GPIO4: length 47.6
  TOP w0.109: J25.33 33.15,58.58 v1(32.39,57.81) ; U60.34 16.27,26.44 16.83,25.89 20.92,25.89 21.99,24.82 v1(21.99,24.71)
  L6_IN2 w0.114: v1(32.39,57.81) 32.05,57.47 32.05,45.48 27.27,40.7 27.27,29.97 22,24.71 v1(21.99,24.71)
FT_IO_01: length 24.1
  TOP w0.109: v1(13.57,74.71) 14.9,73.39 14.9,68.83 17.41,66.32 27.2,66.32 29.15,64.36 J25.14
  BOTTOM w0.102: R390.2 13.57,74 v1(13.57,74.71)
FT_IO_02: length 23.9
  TOP w0.109: J25.16 29.55,64.46 27.36,66.66 17.61,66.66 15.33,68.95 15.33,74.06 v1(14.66,74.73)
  BOTTOM w0.102: R391.2 14.66,73.97 v1(14.66,74.73)
FT_IO_03: length 23.8
  TOP w0.109: v1(15.41,74.72) 15.76,74.37 15.76,69.09 17.79,67.06 27.43,67.06 29.84,64.65 29.84,64.05 29.95,63.94 J25.18
  BOTTOM w0.102: v1(15.41,74.72) 15.76,74.37 R392.2
FT_IO_04: length 21
  TOP w0.109: J25.22 30.75,63.98 30.85,64.08 30.85,64.95 27.38,68.42 18.94,68.42 17.96,69.4 17.96,71.37 v1(18.44,71.85)
  BOTTOM w0.109: R393.2 18.32,71.96 v1(18.44,71.85)
FT_IO_05: length 18.8
  TOP w0.109: v1(18.59,69.88) 18.59,69.43 19.16,68.86 27.51,68.86 31.15,65.22 J25.24
  BOTTOM w0.102: R395.2 18.48,69.76 v1(18.59,69.88)
FT_IO_06: length 20.1
  TOP w0.109: J25.26 31.55,65.38 27.65,69.29 19.48,69.29 19.22,69.54 v1(19.22,69.86)
  BOTTOM w0.102: R396.2 16.91,67.55 v1(19.22,69.86)
FT_IO_07: length 21.2
  TOP w0.109: J25.28 31.95,64 31.84,64.11 31.84,65.63 32.22,66.01 v1(32.34,66.01)
  BOTTOM w0.109: R397.2 15.75,63.68 23,63.68 25.33,66.01 v1(32.34,66.01)
FT_IO_08: length 21.6
  TOP w0.109: J25.32 32.75,63.96 32.81,64.01 32.81,64.9 v1(32.33,65.39)
  BOTTOM w0.109: R398.2 14.9,63.45 23.35,63.45 25.48,65.58 32.13,65.58 v1(32.33,65.39)
FT_IO_09: length 25.8
  TOP w0.109: v1(33.28,65.13) 33.06,64.91 33.06,64.04 33.15,63.95 J25.34
  BOTTOM w0.109: R399.2 10.85,63.75 11.43,63.17 23.56,63.17 25.33,64.94 33.09,64.94 v1(33.28,65.13)
FT_IO_10: length 26.1
  TOP w0.102: v1(33.5,64.4) 33.5,64.36 33.55,64.3 J25.36
  BOTTOM w0.109: R400.2 11.08,62.93 23.75,62.93 25.51,64.69 32.85,64.69 33.14,64.4 v1(33.5,64.4)
FT_IO_11: length 1.7
  TOP w0.109: R401.2 33.96,63.49 J25.38
FT_IO_NINT: length 53.8
  TOP w0.109: U60.29 14.89,23.7 14.89,23.69 v1(13.97,23.69)
  L6_IN2 w0.114: v1(13.97,23.69) 13.97,36.19 4.07,46.08 4.07,67.12 v1(4.02,67.17)
  BOTTOM w0.102: v1(4.02,67.17) 4.1,67.25 R449.1
FT_IO_NRST: length 92
  TOP w0.109: J25.37 33.95,60.02 33.85,59.92 33.85,59.39 34.19,59.06 v1(34.35,59.06) ; U60.23 19.81,20.7 20.28,21.17 v1(20.28,21.56)
  L6_IN2 w0.114: v1(34.35,59.06) 32.6,57.3 32.6,45.43 27.83,40.67 27.83,29.16 20.47,21.8 20.47,21.76 v1(20.28,21.56)
  BOTTOM w0.109: v1(34.35,59.06) 32.38,57.08 30.05,57.08 29.69,57.45 24.41,57.45 20.06,61.8 8.11,61.8 3.5,66.41 3.5,71.04 6.45,73.99 R412.1
FT_IOEXP_SCL: length 3.8
  BOTTOM w0.109: U70.19 9.46,66.95 R363.2
FT_IOEXP_SDA: length 3.8
  BOTTOM w0.109: R364.2 7.81,65.98 8.53,66.7 8.53,67.95 8.91,68.32 U70.20
FT_ONOFF_B: length 33.4
  TOP w0.102: U60.24 17.84,21.2 v1(17.73,21.09)
  L6_IN2 w0.114: v1(17.73,21.09) 17.29,21.53 17.29,46.24 18.69,47.64 v1(19.78,47.64)
  BOTTOM w0.109: R382.1 22.67,46.71 22.4,46.43 21.42,46.43 20.21,47.64 v1(19.78,47.64)
FT_OSCI: length 7.6
  TOP w0.109: X1.1 7.3,10.39 8.29,11.37 8.29,13.04 C252.1 8.43,14.54 9.49,14.54 9.77,14.82 U60.2
FT_OSCO: length 4.8
  TOP w0.109: U60.3 10.27,14.77 9.78,14.29 9.01,14.29 8.91,14.18 C253.1 8.91,12.59 X1.3
FT_PWREN: length 3
  TOP w0.109: TP93.1 6,19.7 U60.60
FT_REMOTE_SEL: length 11.9
  BOTTOM w0.102: U67.2 21.78,67.72 22.15,68.1 R409.2
  BOTTOM w0.109: R394.2 22.95,70.87 23.55,70.27 TP134.1 22.81,68.54 R409.2
FT_RESET_B: length 48.2
  TOP w0.102: v1(20.21,19.86) 20.04,19.7 U60.21
  TOP w0.109: J25.35 33.55,59.23 v1(34.36,58.42)
  L6_IN2 w0.114: v1(20.21,19.86) 28.29,27.95 28.29,40.48 33.05,45.24 33.05,57.11 v1(34.36,58.42)
FT_SCL: length 79.3
  TOP w0.109: R333.2 20.86,22.2 v1(20.24,22.2) U60.26 ; v1(29.17,46.26) 29.17,42 TP130.1 ; v1(30.38,58.94) 30.87,59.42 30.87,59.93 30.75,60.04 J25.21
  L6_IN2 w0.114: v1(30.38,58.94) 29.3,57.86 29.3,46.39 v1(29.17,46.26) 28.33,46.26 24.67,42.6 24.67,31.23 19.78,26.34 19.78,22.65 v1(20.24,22.2)
  BOTTOM w0.109: R363.1 6.65,64.89 6.65,64.37 8.67,62.34 20.48,62.34 24.58,58.24 29.68,58.24 v1(30.38,58.94) ; R441.1 29.17,46.41 v1(29.17,46.26)
FT_SDA: length 82.5
  TOP w0.102: U60.28 17.64,23.2 17.48,23.04 17.48,22.78 17.57,22.7 U60.27
  TOP w0.109: v1(28.61,45.81) 28.61,41.48 TP129.1 ; R334.2 20.81,23.2 v1(20.23,23.2) U60.28 ; J25.23 31.15,59.02 v1(30.4,58.27)
  L6_IN2 w0.114: v1(30.4,58.27) 29.63,57.5 29.63,46.04 29.41,45.81 v1(28.61,45.81) 25.2,42.4 25.2,31.01 20.23,26.04 v1(20.23,23.2)
  BOTTOM w0.109: R364.1 6.11,65.44 6.11,64.38 8.4,62.09 20.31,62.09 24.52,57.88 30.01,57.88 v1(30.4,58.27) ; R442.1 v1(28.61,45.81)
FT_SUSPEND_B: length 46.8
  TOP w0.102: U60.36 15.27,28.26 v1(14.96,28.58)
  L6_IN2 w0.114: v1(14.96,28.58) 15.15,28.77 15.15,50.01 18.94,53.8 18.94,68.32 20.57,69.94 v1(20.69,69.94)
  BOTTOM w0.109: R408.1 20.69,69.63 v1(20.69,69.94) 21,70.25 TP96.1
FT_SYS_NRST: length 64.6
  TOP w0.102: U60.22 v1(17.73,20.2)
  TOP w0.109: TP133.1 21.46,19.41 21.46,20.09 21.18,20.37 19.74,20.37 19.57,20.2 U60.22
  L6_IN2 w0.114: v1(20.72,75.16) 20.27,74.71 20.27,74.11 21.26,73.11 21.26,51.77 16.95,47.46 16.95,20.98 v1(17.73,20.2)
  BOTTOM w0.102: U66.2 21.21,74.66 v1(20.72,75.16)
FT_USB_DN: length 1.6
  TOP w0.102: U62.C2 14.54,9.16 14.67,9.28 14.67,9.96 R327.1
FT_USB_DP: length 1.6
  TOP w0.102: R328.1 14.88,10.06 14.88,9.22 14.94,9.16 U62.C1
FTA_TCK: length 39.2
  TOP w0.109: U60.16 v1(16.77,16.88)
  L6_IN2 w0.114: v1(16.77,16.88) 18.26,18.37 18.26,46.56 18.74,47.04 v1(19.74,47.04)
  BOTTOM w0.109: v1(19.74,47.04) 17.69,47.04 15.2,49.54 U7.2
FTA_TDI: length 35.3
  TOP w0.109: U60.17 v1(18.8,17.01)
  L6_IN2 w0.114: v1(18.73,46.41) 18.61,46.28 18.61,17.2 v1(18.8,17.01)
  BOTTOM w0.109: v1(18.73,46.41) 18.68,46.46 17.83,46.46 15.15,49.14 U7.3
FTA_TDO: length 35.4
  TOP w0.109: U60.18 19.78,18.2 v1(19.93,18.04)
  L6_IN2 w0.114: v1(19.93,18.04) 19.94,18.04 20.34,18.44 20.34,18.81 19.33,19.82 19.33,44.81 v1(19.74,45.22)
  BOTTOM w0.109: U7.5 15.19,48.34 18.3,45.22 v1(19.74,45.22)
FTA_TMS: length 35.3
  TOP w0.109: U60.19 19.83,18.7 v1(19.9,18.63)
  L6_IN2 w0.114: v1(19.9,18.63) 19.83,18.7 19.82,18.7 18.99,19.52 18.99,45.24 19.56,45.81 v1(19.74,45.81)
  BOTTOM w0.109: v1(19.74,45.81) 18.12,45.81 15.19,48.74 U7.4
FTDIC_RX: length 9.9
  TOP w0.203: U61.15 12.6,34.42 v1(12.79,34.22)
  TOP w0.254: D17.C v1(12.91,28.86) 13.24,28.54 13.41,28.54 13.77,28.18 U60.39
  BOTTOM w0.203: v1(12.91,28.86) 12.65,29.12 12.65,34.08 v1(12.79,34.22)
FTDIC_TX: length 10.8
  TOP w0.203: U61.13 11.8,34.9 11.62,34.72 11.62,34.31 12.35,33.58 12.35,32.83 13.13,32.05 14.28,32.05 14.64,31.68 14.64,30.69 D16.C
  TOP w0.254: D16.C 14.27,28.94 U60.38
FTDID_RX: length 19.2
  TOP w0.203: U60.52 5.28,23.7 D21.C 5.28,23.67 v1(5.28,22.59) ; v1(12.1,34.51) 12.2,34.61 U61.14
  BOTTOM w0.203: v1(5.28,22.59) 4.56,23.31 4.56,25.99 12.1,33.53 v1(12.1,34.51)
FTDID_TX: length 12.6
  TOP w0.203: D20.C 8.42,31.89 8.42,34.23 10.06,35.87 U61.12
  TOP w0.254: D20.C 9.27,28.24 U60.48
GPIO1_IO00: length 69.2
  TOP w0.102: J1.25 75.89,107.03 75.86,107 75.86,106.17 75.42,105.73 v1(75.14,105.73)
  BOTTOM w0.109: v1(75.14,105.73) 79.21,101.67 105.21,101.67 105.69,101.19 105.69,92.8 109.34,89.16 113.27,89.16 115.91,86.51 R315.1
GPIO1_IO12: length 123.3
  TOP w0.102: R308.1 v1(181.73,90.34) ; J1.20 74.69,111.44 v1(74.64,111.49)
  BOTTOM w0.109: v1(74.64,111.49) 75.17,112.02 77.07,112.02 80.53,115.48 123.92,115.48 132.71,106.69 162.69,106.69 169.54,99.84 176.5,99.84 181.73,94.61 v1(181.73,90.34)
HDMI_5V_CN: length 8.6
  TOP w0.254: J17.18 163.06,142.01 163.12,141.94 163.12,141.18 163.84,140.47 165.86,140.47 D10.1 168.17,139.87 R1.2
HDMI_CEC: length 90.3
  TOP w0.109: v1(161.29,131.83) 161.08,131.83 160.28,131.03 160.28,125.57 127.01,92.3 127.01,77.84 120.91,71.74 116.57,71.74 116.5,71.81 J4.49
  TOP w0.254: Q5.2 165.13,131.83 R186.2 v1(165.9,131.8) 166.68,131.8 D32.A
  BOTTOM w0.102: v1(161.29,131.83) 161.91,132.45 165.25,132.45 v1(165.9,131.8)
HDMI_CEC_CN: length 13.5
  TOP w0.254: D32.C 165.93,135.1 Q5.3 163.2,136.38 163.2,138.26 D13.1 160.55,140.9 J17.13
  TOP w0.381: D32.C 166.89,134.14 R174.2
HDMI_CLKN_CN: length 5.6
  TOP w0.091: U46.A4 158.61,138.02 158.61,138.55 159.69,139.62 159.69,140.97 160.06,141.33 J17.12
HDMI_CLKP_CN: length 5.6
  TOP w0.091: U46.A3 158.35,138.02 158.35,138.66 159.42,139.73 159.42,140.98 159.06,141.35 J17.10
HDMI_DDC_SCL: length 82.5
  TOP w0.109: R177.2 163.08,126.47 R181.1 ; R177.2 161.89,126.28 v1(162.29,125.88) ; R177.2 161.89,127.66 TP89.1 ; J4.41 116.32,70.2 116.36,70.25 121.5,70.25 128.65,77.41 128.65,92.59 159.46,123.4 160.66,123.4 v1(160.72,123.34)
  L3_IN1 w0.114: v1(160.72,123.34) 162.29,124.9 v1(162.29,125.88)
HDMI_DDC_SCL_CN: length 25
  TOP w0.109: v1(164.05,138.33) D12.1 163.53,139.04 161.55,141.01 J17.15 ; R179.2 171.69,126.55 U48.7 168.82,126.55 v1(167.76,125.48)
  L3_IN1 w0.114: v1(164.05,138.33) 164.62,137.76 164.62,135.99 167.76,132.86 v1(167.76,125.48)
HDMI_DDC_SDA: length 79.5
  TOP w0.102: R183.1 161.9,125.27 R178.2 161.89,123.83 TP90.1
  TOP w0.109: TP90.1 159.38,123.78 128.34,92.73 128.34,77.66 121.23,70.55 116.38,70.55 116.33,70.6 J4.43
HDMI_DDC_SDA_CN: length 24.9
  TOP w0.109: J17.16 162.06,141.05 163.19,139.91 164.8,139.91 D11.1 165.7,139 v1(165.7,138.23) ; R180.2 171.69,125.9 U48.6 168.87,125.9 v1(168.39,125.42)
  L3_IN1 w0.114: v1(168.39,125.42) 168.39,132.92 166.55,134.75 166.55,137.39 v1(165.7,138.23)
HDMI_HPD: length 81.1
  TOP w0.109: U79.4 160.59,129.16 160.59,125.38 127.34,92.12 127.34,77.49 121.32,71.47 116.52,71.47 116.45,71.4 J4.47
HDMI_HPD/EARC-: length 3.6
  TOP w0.102: R175.2 161.23,135 C162.2 161.22,135.89 TP95.1 160.53,136.71 U30.C2
HDMI_HPD_5V: length 4.1
  TOP w0.254: U79.2 162.32,132.25 R176.1 162.71,132.26 162.95,132.5 162.95,134.06 162.75,134.25 R175.1
HDMI_HPD_CN: length 6.8
  TOP w0.102: v1(160.86,138.47) 160.53,138.13 U30.A2
  TOP w0.109: J17.19 163.55,141.63 163.91,141.28 v1(163.91,141.21)
  L3_IN1 w0.114: v1(163.91,141.21) 163.47,141.21 160.86,138.61 v1(160.86,138.47)
HDMI_TXCN: length 82.5
  TOP w0.091: J4.59 116.53,73.81 116.58,73.86 118.52,73.86 125.17,80.51 125.17,93.06 157.55,125.44 157.55,131.26 158.64,132.35 158.64,137.11 U46.C4
HDMI_TXCP: length 82.5
  TOP w0.091: J4.61 116.53,74.2 116.6,74.13 118.41,74.13 124.9,80.62 124.9,93.17 157.28,125.55 157.28,131.37 158.37,132.46 158.37,134.9 158.22,135.05 158.22,135.26 158.37,135.4 158.37,135.61 158.22,135.76 158.22,135.97 158.37,136.11 158.37,136.32 158.22,136.47 158.22,136.68 158.37,136.82 158.37,137.06 158.28,137.15 U46.C3
HDMI_TXN0: length 82.5
  TOP w0.091: U46.C2 157.81,137.08 157.81,133.19 156.16,131.54 156.16,126.12 123.87,93.83 123.87,93.21 123.62,92.96 123.59,92.96 123.5,92.87 123.5,92.7 123.59,92.61 123.62,92.61 123.87,92.36 123.87,91.96 123.62,91.72 123.59,91.72 123.5,91.63 123.5,91.45 123.59,91.36 123.62,91.36 123.87,91.12 123.87,90.72 123.62,90.47 123.59,90.47 123.5,90.38 123.5,90.21 123.59,90.12 123.62,90.12 123.87,89.87 123.87,89.47 123.62,89.23 123.59,89.23 123.5,89.14 123.5,88.96 123.59,88.87 123.62,88.87 123.87,88.63 123.87,88.23 123.62,87.98 123.59,87.98 123.5,87.89 123.5,87.72 123.59,87.63 123.62,87.63 123.87,87.38 123.87,80.84 118.09,75.07 116.59,75.07 116.53,75 J4.65
HDMI_TXN0_CN: length 5.3
  TOP w0.091: U46.A2 157.81,138.02 157.81,139.25 158.2,139.63 158.2,140.98 158.55,141.34 J17.9
HDMI_TXN1: length 82.6
  TOP w0.091: U47.C4 156.21,137.09 156.21,133.38 154.69,131.87 154.69,126.77 122.08,94.15 122.08,86.47 121.83,86.22 121.46,86.22 121.37,86.13 121.37,85.95 121.46,85.87 121.83,85.87 122.08,85.62 122.08,85.22 121.83,84.98 121.46,84.98 121.37,84.89 121.37,84.71 121.46,84.62 121.83,84.62 122.08,84.38 122.08,83.98 121.83,83.73 121.46,83.73 121.37,83.64 121.37,83.47 121.46,83.38 121.83,83.38 122.08,83.13 122.08,82.73 121.83,82.49 121.48,82.49 121.39,82.4 121.39,82.22 121.48,82.13 121.83,82.13 122.08,81.89 122.08,80.74 117.6,76.27 116.59,76.27 116.53,76.2 J4.71
HDMI_TXN1_CN: length 5.3
  TOP w0.091: U47.A4 156.21,138.03 156.21,138.55 156.71,139.05 156.71,140.99 157.06,141.34 J17.6
HDMI_TXN2: length 82.4
  TOP w0.091: U47.C2 155.41,137.09 155.41,134.41 153.22,132.22 153.22,127.33 119.73,93.84 119.73,92.12 119.82,92.03 120.39,92.03 120.63,91.78 120.63,91.38 120.39,91.14 119.82,91.14 119.73,91.05 119.73,90.87 119.82,90.78 120.39,90.78 120.63,90.54 120.63,90.14 120.39,89.89 119.82,89.89 119.73,89.8 119.73,89.63 119.82,89.54 120.39,89.54 120.63,89.29 120.63,88.89 120.39,88.65 119.82,88.65 119.73,88.56 119.73,88.38 119.82,88.29 120.39,88.29 120.63,88.05 120.63,87.65 120.39,87.4 119.82,87.4 119.73,87.31 119.73,80.14 117.05,77.46 116.58,77.46 116.53,77.4 J4.77
HDMI_TXN2_CN: length 5.2
  TOP w0.091: U47.A2 155.41,138.03 155.41,138.63 155.2,138.85 155.2,141 155.55,141.36 J17.3
HDMI_TXP0: length 82.4
  TOP w0.091: U46.C1 157.55,137.09 157.55,136.57 157.46,136.48 157.45,136.48 157.36,136.39 157.36,136.22 157.45,136.13 157.46,136.13 157.55,136.04 157.55,135.86 157.46,135.77 157.45,135.77 157.36,135.68 157.36,135.5 157.45,135.42 157.46,135.42 157.55,135.33 157.55,135.15 157.42,135.03 157.42,134.74 157.55,134.62 157.55,133.3 155.89,131.65 155.89,126.23 123.6,93.94 123.6,93.32 123.51,93.23 123.48,93.23 123.23,92.98 123.23,92.58 123.48,92.34 123.51,92.34 123.6,92.25 123.6,92.07 123.51,91.98 123.48,91.98 123.23,91.74 123.23,91.34 123.48,91.1 123.51,91.1 123.6,91.01 123.6,90.83 123.51,90.74 123.48,90.74 123.23,90.49 123.23,90.1 123.48,89.85 123.51,89.85 123.6,89.76 123.6,89.58 123.51,89.49 123.48,89.49 123.23,89.25 123.23,88.85 123.48,88.61 123.51,88.61 123.6,88.52 123.6,88.34 123.51,88.25 123.48,88.25 123.23,88.01 123.23,87.61 123.48,87.36 123.51,87.36 123.6,87.27 123.6,80.95 117.98,75.33 116.6,75.33 116.53,75.4 J4.67
HDMI_TXP0_CN: length 5.3
  TOP w0.091: J17.7 157.55,141.35 157.93,140.97 157.93,139.74 157.55,139.36 157.55,138.02 U46.A1
HDMI_TXP1: length 82.6
  TOP w0.091: U47.C3 155.94,137.09 155.94,136.84 155.78,136.67 155.78,136.48 155.94,136.32 155.94,136.13 155.78,135.96 155.78,135.77 155.94,135.61 155.94,135.41 155.78,135.25 155.78,135.06 155.94,134.89 155.94,133.49 154.43,131.98 154.43,126.88 121.81,94.26 121.81,86.58 121.72,86.49 121.34,86.49 121.1,86.24 121.1,85.84 121.34,85.6 121.72,85.6 121.81,85.51 121.81,85.33 121.72,85.24 121.34,85.24 121.1,85 121.1,84.6 121.34,84.35 121.72,84.35 121.81,84.27 121.81,84.09 121.72,84 121.34,84 121.1,83.75 121.1,83.35 121.34,83.11 121.72,83.11 121.81,83.02 121.81,82.84 121.72,82.75 121.37,82.75 121.13,82.51 121.13,82.11 121.37,81.86 121.72,81.86 121.81,81.78 121.81,80.85 117.49,76.53 116.6,76.53 116.53,76.6 J4.73
HDMI_TXP1_CN: length 5.3
  TOP w0.091: J17.4 156.06,141.37 156.44,140.99 156.44,139.16 155.94,138.66 155.94,138.03 U47.A3
HDMI_TXP2: length 82.4
  TOP w0.091: U47.C1 155.14,137.09 155.14,136.84 154.97,136.66 154.97,136.48 155.14,136.3 155.14,136.13 155.05,136.04 155.05,136.04 154.96,135.95 154.96,135.77 155.05,135.68 155.05,135.68 155.14,135.59 155.14,135.41 154.97,135.24 154.97,135.05 155.14,134.88 155.14,134.52 152.95,132.33 152.95,127.44 119.46,93.95 119.46,92 119.71,91.76 120.28,91.76 120.37,91.67 120.37,91.49 120.28,91.4 119.71,91.4 119.46,91.16 119.46,90.76 119.71,90.52 120.28,90.52 120.37,90.43 120.37,90.25 120.28,90.16 119.71,90.16 119.46,89.91 119.46,89.52 119.71,89.27 120.28,89.27 120.37,89.18 120.37,89 120.28,88.91 119.71,88.91 119.46,88.67 119.46,88.27 119.71,88.03 120.28,88.03 120.37,87.94 120.37,87.76 120.28,87.67 119.71,87.67 119.46,87.43 119.46,80.25 116.94,77.73 116.6,77.73 116.53,77.81 J4.79
HDMI_TXP2_CN: length 5.2
  TOP w0.091: U47.A1 155.14,138.03 155.14,138.52 154.93,138.74 154.93,140.99 154.55,141.36 J17.1
HDMI_UTILITY/EARC+: length 2.2
  TOP w0.102: C161.2 160.15,135.82 TP94.1 160.13,136.06 U30.C1
HDMI_UTILITY_CN: length 5.4
  TOP w0.102: U30.A1 160.13,138.47 v1(160.15,138.49) ; v1(161.11,141.53) 161.06,141.59 J17.14
  L3_IN1 w0.114: v1(161.11,141.53) 161.11,141.52 161.11,139.45 v1(160.15,138.49)
HP_J_D: length 29.1
  TOP w0.203: R189.2 v1(198.13,32.95) ; J18.5 192.92,10.24 TVS5.2 194.85,16.68 194.85,18.31 198.11,21.57 v1(198.11,22.78) R187.2
  L6_IN2 w0.203: v1(198.11,22.78) 197.35,23.55 197.35,32.22 198.08,32.95 v1(198.13,32.95)
HP_J_L: length 12.7
  TOP w0.203: C176.2 195.93,20.81 L11.2 194.92,20.04 191.23,16.35 191.23,15.94 TVS4.2 190.02,13.17 J18.4
HP_J_MIC: length 33.8
  TOP w0.203: C193.1 200.3,31.91 L13.2 200.98,30.88 201.75,30.11 201.75,16.44 199.97,14.67 TVS3.2 198.94,13.7 199.95,12.69 199.95,6.62 197.53,4.21 J18.1
HP_J_R: length 14
  TOP w0.203: J18.3 196.03,14.16 TVS6.2 v1(195.15,14.65) ; v1(190.51,20.22) 190.51,20.95 C179.1
  TOP w0.254: C179.1 191.49,20.95 L12.2
  L6_IN2 w0.203: v1(190.51,20.22) 190.51,19.29 v1(195.15,14.65)
HP_JD: length 3.1
  TOP w0.203: U50.7 195.15,31.32 R189.1
HP_L: length 3.5
  TOP w0.203: U50.31 193.21,27.02 194.07,26.17 C177.1
HP_MIC1N: length 3.9
  TOP w0.203: U50.4 195.86,29.82 C181.2 C183.1
HP_MIC1P: length 3.6
  TOP w0.203: C191.1 C192.1 195.98,28.52 195.68,28.82 U50.2
HP_MIC_P: length 3.2
  TOP w0.203: C191.2 199.31,29.62 R201.2 199.42,30.74 L13.1
HP_R: length 3.3
  TOP w0.203: C178.1 192.21,24.94 U50.29
HPL: length 2.8
  TOP w0.203: L11.1 194.79,21.7 R190.2 193.77,22.91 C177.2
HPR: length 2.7
  TOP w0.203: L12.1 191.75,21.7 R196.1 192.68,23.1 C178.2
I2C2_SCL: length 259.5
  TOP w0.102: R162.2 v1(60.4,125.05) ; R172.2 v1(131.72,124.88) ; R167.2 v1(35.65,125.1)
  TOP w0.109: U5.2 177.93,101.69 R7.2 176.97,103.18 176.63,103.52 175.35,103.52 TP5.1 169.53,102.7 153.85,87.03 147.53,87.03 v1(146.23,85.73) ; J3.55 99.82,59.76 99.7,59.64 v1(99.7,59.51)
  L6_IN2 w0.114: v1(146.23,85.73) 147.2,86.7 147.2,109.39 v1(131.72,124.88)
  BOTTOM w0.102: v1(146.23,85.73) 146.19,85.77 R153.2
  BOTTOM w0.109: v1(146.23,85.73) 146.23,76.85 143.18,73.8 118.98,73.8 118.64,74.14 113.51,74.14 112.41,75.24 108.93,75.24 100.58,66.89 99.66,66.89 98.11,65.34 98.11,61.25 99.7,59.66 v1(99.7,59.51) ; v1(35.65,125.1) 35.65,125.01 36.16,124.51 36.9,124.51 38.16,125.77 59.68,125.77 v1(60.4,125.05) 61.01,124.43 61.98,124.43 63.94,126.4 130.2,126.4 v1(131.72,124.88)
I2C2_SCL_3V3: length 217.8
  TOP w0.102: R61.1 v1(63.74,31.48) 64.37,31.48 R58.1
  TOP w0.109: R133.1 161.13,114.71 161.9,115.47 v1(171.27,115.47) ; U5.10 180.97,101.69 v1(181.46,102.18) 181.85,102.57 R11.2
  L6_IN2 w0.114: v1(171.37,37.61) 171.97,38.22 171.97,98.07 176.08,102.18 v1(181.46,102.18)
  BOTTOM w0.109: v1(171.37,37.61) 162.35,37.61 158.59,41.36 75.04,41.36 65.15,31.48 v1(63.74,31.48) ; v1(181.46,102.18) 182.11,102.83 182.11,104.8 171.44,115.47 v1(171.27,115.47)
I2C2_SDA: length 257
  TOP w0.102: R8.2 176.95,101.2 176.8,101.05 174.78,101.05 TP6.1 ; R160.2 61.44,125.72 v1(61.44,124.99) ; R166.2 v1(36.72,125.1) ; R170.2 v1(132.83,124.88)
  TOP w0.109: U5.3 177.81,101.29 177.54,101.57 R8.2 ; v1(147.16,85.7) 148.13,86.67 154.36,86.67 169,101.31 TP6.1 ; v1(99.74,58.89) 100.18,59.33 100.18,59.84 100.22,59.88 J3.57
  L6_IN2 w0.114: v1(147.16,85.7) 147.72,86.26 147.72,109.99 v1(132.83,124.88)
  BOTTOM w0.102: v1(147.16,85.7) 147.24,85.79 R152.2
  BOTTOM w0.109: v1(132.83,124.88) 130.95,126.76 63.87,126.76 62.1,124.99 v1(61.44,124.99) 60.36,126.07 37.71,126.07 36.75,125.1 v1(36.72,125.1) ; v1(99.74,58.89) 100.13,59.29 100.13,60.19 99.01,61.31 99.01,65.61 99.87,66.48 100.7,66.48 107.56,73.33 114.91,73.33 115.44,73.86 118.19,73.86 118.61,73.43 143.31,73.43 147.16,77.29 v1(147.16,85.7)
I2C2_SDA_3V3: length 220.5
  TOP w0.102: R59.1 64.38,32.58 v1(63.7,32.58) R62.1
  TOP w0.109: U5.9 181.33,101.29 v1(181.55,101.51) R12.2 ; v1(171.29,116.25) 161.64,116.25 160.03,114.64 R134.1
  L6_IN2 w0.114: v1(181.55,101.51) 181.48,101.51 181.37,101.62 176.07,101.62 172.35,97.89 v1(172.35,37.74)
  BOTTOM w0.109: v1(171.29,116.25) 182.47,105.08 182.47,102.43 v1(181.55,101.51) ; v1(63.7,32.58) 65.71,32.58 74.81,41.69 159.04,41.69 162.68,38.05 172.24,38.05 172.35,37.94 v1(172.35,37.74)
I2C3_SCL: length 256.7
  TOP w0.102: R173.2 v1(107.9,125.11) 108.77,124.24 108.77,118.3 v1(108.33,117.86) ; R9.2 v1(177.83,100.47) ; R306.1 v1(184.73,89.57) ; R198.1 v1(185.54,32.79) ; R164.2 84.27,125.12 v1(84.32,125.07)
  TOP w0.109: TP7.1 176.81,99.91 176.95,100.04 R9.2 ; v1(100.66,58.96) 100.84,58.96 101.11,59.24 101.11,59.74 101.02,59.83 J3.61 ; U5.4 178.51,100.89 178.09,100.47 v1(177.83,100.47)
  L6_IN2 w0.114: v1(177.83,100.47) 180.4,100.47 183.66,97.21 183.66,90.65 184.73,89.58 v1(184.73,89.57) 184.74,89.57 185.27,89.04 185.27,33.06 v1(185.54,32.79) ; v1(100.66,58.96) 100.67,58.96 101.07,59.36 101.07,65.06 106.36,70.35 106.36,94.67 107.49,95.81 107.49,117.02 v1(108.33,117.86)
  BOTTOM w0.109: v1(177.83,100.47) 178.52,101.16 178.52,103.99 165.39,117.12 108.98,117.12 108.33,117.78 v1(108.33,117.86) ; v1(84.32,125.07) 85.15,124.25 86.92,124.25 88.35,125.68 107.34,125.68 v1(107.9,125.11)
